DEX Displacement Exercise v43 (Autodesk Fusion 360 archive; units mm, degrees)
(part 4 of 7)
sketch "Sketch38" plane through (0, 0, 0) normal (0, 0, 1) x axis (1, 0, 0)
  line L1 (-32.5, 52.5) -> (-32.5, -27.5)
  line L2 (87.5, -27.5) -> (-32.5, -27.5)
  line L3 (-17.5, -17.5) -> (-17.5, -27.5)
  line L4 (17.5, -17.5) -> (-17.5, -17.5)
  line L5 (17.5, 17.5) -> (17.5, -17.5)
  line L6 (-17.5, 17.5) -> (17.5, 17.5)
  line L7 (-17.5, 27.5) -> (-17.5, 17.5)
  line L8 (-32.5, 27.5) -> (-17.5, 27.5)
  line L9 (87.5, -27.5) -> (-17.5, -27.5)
  line L10 (-32.5, 52.5) -> (-32.5, 27.5)
  line L11 (17.5, 0) -> (0, 0)
  line L12 (-32.8, -22.8) -> (-32.8, 22.8)
  line L13 (40.8319, 85.8319) -> (-15.5681, 85.8319)
  line L14 (40.8319, 29.4319) -> (40.8319, 85.8319)
  line L15 (-15.5681, 29.4319) -> (40.8319, 29.4319)
  line L16 (-15.5681, 85.8319) -> (-15.5681, 29.4319)
  line L17 (12.6319, 57.6319) -> (12.6319, 85.8319)
  line L18 (40.8319, 57.6319) -> (12.6319, 57.6319)
  line L19 (-17.6, 17.4) -> (17.4, 17.4)
  line L20 (-17.6, 27.4) -> (-17.6, 17.4)
  line L21 (-19.3, 27.4) -> (-17.6, 27.4)
  line L22 (-19.3, 15.7) -> (-19.3, 27.4)
  line L23 (15.7, 15.7) -> (-19.3, 15.7)
  line L24 (15.7, -15.7) -> (15.7, 15.7)
  line L25 (-19.3, -15.7) -> (15.7, -15.7)
  line L26 (-19.3, -27.4) -> (-19.3, -15.7)
  line L27 (-17.6, -27.4) -> (-19.3, -27.4)
  line L28 (-17.6, -17.4) -> (-17.6, -27.4)
  line L29 (17.4, -17.4) -> (-17.6, -17.4)
  line L30 (17.4, 17.4) -> (17.4, -17.4)
  line L31 (27.5, -27.4) -> (-17.6, -27.4)
  line L32 (27.5, 27.4) -> (27.5, -27.4)
  line L33 (-17.6, 27.4) -> (27.5, 27.4)
  line L34 (0, 0) -> (12.6319, 57.6319)
  line L35 (36.2019, 81.2019) -> (-10.9381, 81.2019)
  line L36 (36.2019, 34.0619) -> (36.2019, 81.2019)
  line L37 (-10.9381, 34.0619) -> (36.2019, 34.0619)
  line L38 (-10.9381, 81.2019) -> (-10.9381, 34.0619)
  line L39 (-17.5, 37.4) -> (-17.5, 27.5)
  line L40 (-32.5, 37.4) -> (-17.5, 37.4)
  line L41 (-40.5, 15.7) -> (-19.3, 15.7)
  line L42 (-40.5, 27.4) -> (-40.5, 15.7)
  line L43 (-19.3, 27.4) -> (-40.5, 27.4)
  line L44 (-40.5, -27.4) -> (-19.3, -27.4)
  line L45 (-40.5, -15.7) -> (-40.5, -27.4)
  line L46 (-19.3, -15.7) -> (-40.5, -15.7)
  line L47 (-40.5, -15.7) -> (-40.5, 15.7)
  line L48 (-19.3, 35.6) -> (-19.3, 27.4)
  line L49 (-40.5, 35.6) -> (-19.3, 35.6)
  line L50 (-40.5, 27.4) -> (-40.5, 35.6)
  line L51 (-40.5, 37.3) -> (-40.5, 35.6)
  line L52 (-17.6, 37.3) -> (-40.5, 37.3)
  line L53 (-17.6, 27.4) -> (-17.6, 37.3)
  line L54 (-17.6, -27.6) -> (-17.6, -27.4)
  line L55 (27.5, -27.6) -> (-17.6, -27.6)
  line L56 (27.5, -27.4) -> (27.5, -27.6)
  line L57 (27.5, -29.2) -> (27.5, -27.6)
  line L58 (-40.5, -29.2) -> (27.5, -29.2)
  line L59 (-40.5, -27.4) -> (-40.5, -29.2)
  line L60 (-19.3, -29.2) -> (-19.3, -27.4)
  line L61 (-27.1727, 28.6279) -> (8.2492, 62.2493)
  line L62 (36.6558, 14.6378) -> (18.5441, 59.9928)
  line L63 (-15.5681, 27.4) -> (-15.5681, 29.4319)
  line L64 (-17.6, 29.4319) -> (-15.5681, 29.4319)
  line L65 (-17.6, 47.4) -> (-17.6, 37.3)
  line L66 (-40.5, 47.4) -> (-17.6, 47.4)
  line L67 (-40.5, 37.3) -> (-40.5, 47.4)
  line L68 (-32.6, 47.4) -> (-32.6, 37.3)
  circle C1 centre (0, 0) radius 13.369
  circle C2 centre (0, 0) radius 39.4704
  circle C3 centre (-32.8, -22.8) radius 9.7
  circle C4 centre (-32.8, 22.8) radius 9.7
  circle C5 centre (12.6319, 57.6319) radius 6.3662
  circle C6 centre (0, 0) radius 21
  circle C7 centre (0, 0) radius 15
  circle C8 centre (-32.8, -22.8) radius 3
  circle C9 centre (-32.8, 22.8) radius 3
  circle C10 centre (-32.8, 22.8) radius 4.5
  circle C11 centre (-32.8, -22.8) radius 4.5
  circle C12 centre (0, 0) radius 19.5
  circle C13 centre (-12.5, -22.5) radius 2.7
  circle C14 centre (36.2019, 34.0619) radius 4
  circle C15 centre (0, 0) radius 15.369
  arc A1 centre (0, 0) radius 24.8793 clockwise from (-19.3, -15.7) to (-19.3, 15.7)
  circle C16 centre (22.5, -22.5) radius 2.7
  circle C17 centre (22.5, 22.5) radius 2.7
  circle C18 centre (-12.5, 22.5) radius 2.7
  circle C19 centre (-10.9381, 34.0619) radius 4
  circle C20 centre (-10.9381, 81.2019) radius 4
  circle C21 centre (36.2019, 81.2019) radius 4
  circle C22 centre (12.6319, 57.6319) radius 19
  circle C23 centre (-27.5, 42.4) radius 2.7
  circle C24 centre (-27.5, 42.4) radius 1.575
  circle C25 centre (-12.5, 22.5) radius 1.575
  circle C26 centre (22.5, 22.5) radius 1.575
  circle C27 centre (22.5, -22.5) radius 1.575
  circle C28 centre (-12.5, -22.5) radius 1.575
  circle C29 centre (-27.5, 42.4) radius 3.75
  circle C30 centre (-12.5, 22.5) radius 3.75
  circle C31 centre (22.5, 22.5) radius 3.75
  circle C32 centre (22.5, -22.5) radius 3.75
  circle C33 centre (-12.5, -22.5) radius 3.75
  point P5 (-17.5, -27.5)
  point P11 (-32.5, 27.5)
  point P6 (-17.5, -17.5)
  point P12 (0, 0)
  point P14 (0, 0)
  point P15 (17.5, 0)
  point P18 (-42.5, -22.8)
  point P19 (-32.8, -32.5)
  point P16 (-32.8, -22.8)
  point P17 (-32.8, 22.8)
  point P20 (-32.8, 22.8)
  point P21 (-32.8, -22.8)
  point P22 (-32.8, 0)
  point P28 (12.6319, 85.8319)
  point P30 (40.8319, 57.6319)
  point P27 (12.6319, 57.6319)
  point P29 (12.6319, 57.6319)
  point P33 (0, 17.5)
  point P32 (0, 0)
  point P38 (17.4, 17.4)
  point P50 (17.4, 17.4)
  point P40 (-17.6, 27.4)
  point P53 (-17.6, 27.4)
  point P56 (12.6319, 57.6319)
  point P57 (0, 0)
  point P62 (12.6319, 81.2019)
  point P63 (36.2019, 57.6319)
  point P60 (36.2019, 34.0619)
  point P64 (36.2019, 34.0619)
  point P66 (-32.5, 37.4)
  point P41 (-19.3, 27.4)
  point P70 (-19.3, 27.4)
  point P45 (-19.3, -15.7)
  point P73 (-19.3, -15.7)
  point P74 (-40.5, -15.7)
  point P72 (-40.5, -15.7)
  point P69 (-40.5, 27.4)
  point P77 (-40.5, 27.4)
  point P80 (-17.6, 27.4)
  point P51 (27.5, -27.4)
  point P83 (27.5, -27.4)
  point P71 (-40.5, -27.4)
  point P86 (-40.5, -27.4)
  point P87 (-19.3, -29.2)
  point P31 (0, 0)
  point P88 (0, 0)
  point P55 (-12.5, -22.5)
  point P91 (-12.5, 22.5)
  point P89 (22.5, -22.5)
  point P90 (22.5, 22.5)
  point P61 (-10.9381, 34.0619)
  point P92 (-10.9381, 34.0619)
  point P58 (-10.9381, 81.2019)
  point P93 (-10.9381, 81.2019)
  point P59 (36.2019, 81.2019)
  point P94 (36.2019, 81.2019)
  point P96 (8.2492, 62.2493)
  point P97 (-27.1727, 28.6279)
  point P98 (18.5441, 59.9928)
  point P99 (36.6558, 14.6378)
  point P1 (0, 0)
  point P67 (0, 0)
  point P101 (-15.5681, 27.4)
  point P102 (-17.6, 29.4319)
  point P78 (-40.5, 37.3)
  point P105 (-40.5, 37.3)
  point P106 (-32.6, 37.3)
  point P107 (-32.6, 47.4)
  point P3 (-32.5, -27.5)
  point P4 (87.5, -27.5)
  point P2 (-32.5, 52.5)
  point P7 (17.5, -17.5)
  point P8 (17.5, 17.5)
  point P9 (-17.5, 17.5)
  point P10 (-17.5, 27.5)
  point P23 (-15.5681, 85.8319)
  point P24 (40.8319, 85.8319)
  point P13 (0, 0)
  point P42 (-19.3, 15.7)
  point P49 (17.4, -17.4)
  point P48 (-17.6, -17.4)
  point P39 (-17.6, 17.4)
  point P65 (-17.5, 37.4)
  point P100 (-27.5, 42.4)
  vertical L1
  perpendicular L1 L2
  coincident L2 P5
  perpendicular L2 L3
  perpendicular L3 L4
  perpendicular L4 L5
  perpendicular L5 L6
  perpendicular L6 L7
  coincident L1 P11
  perpendicular L1 L8
  coincident P6 L7
  concentric C1 C2
  coincident P12 P14
  horizontal L11
  midpoint L5 P15
  equal C3 C4
  coincident C3 P18
  coincident C3 P19
  vertical P16 P19
  horizontal P16 P18
  vertical P16 P17
  coincident P17 P20
  coincident P16 P21
  midpoint L12 P22
  coincident L11 P22
  equal L13 L16
  midpoint L13 P28
  perpendicular L13 L17
  perpendicular L17 L18
  midpoint L14 P30
  coincident P27 P29
  concentric C2 C6
  concentric C2 C7
  midpoint L6 P33
  vertical P32 P33
  perpendicular L13 L16
  parallel L13 L15
  parallel L14 L16
  concentric C3 C8
  concentric C4 C9
  equal C8 C9
  concentric C4 C10
  concentric C3 C11
  equal C10 C11
  parallel L6 L19
  perpendicular L19 L20
  perpendicular L20 L21
  perpendicular L21 L22
  perpendicular L22 L23
  perpendicular L11 L24
  perpendicular L24 L25
  perpendicular L11 L26
  perpendicular L26 L27
  perpendicular L27 L28
  perpendicular L28 L29
  perpendicular L4 L30
  coincident P38 P50
  perpendicular L28 L31
  perpendicular L2 L32
  perpendicular L32 L33
  coincident P40 P53
  concentric C1 C12
  coincident P27 P56
  coincident P12 P57
  perpendicular L35 L36
  parallel L35 L37
  parallel L36 L38
  perpendicular L17 L35
  midpoint L35 P62
  midpoint L36 P63
  coincident L17 P62
  coincident L18 P63
  equal L35 L36
  coincident P60 P64
  perpendicular L8 L39
  coincident L10 P66
  horizontal L40
  concentric C2 C15
  perpendicular L22 L41
  perpendicular L23 L42
  perpendicular L22 L43
  coincident P41 P70
  perpendicular L26 L44
  perpendicular L44 L45
  perpendicular L45 L46
  coincident P45 P73
  coincident L46 P74
  perpendicular L46 L47
  coincident P72 P74
  perpendicular L21 L48
  perpendicular L48 L49
  perpendicular L21 L50
  coincident P69 P77
  perpendicular L49 L51
  perpendicular L50 L52
  perpendicular L49 L53
  coincident P53 P80
  perpendicular L2 L54
  perpendicular L54 L55
  perpendicular L55 L56
  coincident P51 P83
  perpendicular L55 L57
  perpendicular L57 L58
  perpendicular L58 L59
  coincident P71 P86
  coincident L58 P87
  perpendicular L58 L60
  coincident P31 P88
  vertical P55 P91
  vertical P89 P90
  horizontal P55 P89
  horizontal P90 P91
  equal C13 C18
  equal C13 C17
  equal C13 C16
  horizontal L37
  coincident P61 P92
  coincident P58 P93
  coincident P59 P94
  concentric C5 C22
  equal C14 C19
  equal C14 C21
  equal C14 C20
  coincident C5 P96
  coincident C2 P97
  coincident C5 P98
  coincident C2 P99
  tangent C2 L61
  tangent C5 L61
  tangent C5 L62
  tangent C2 L62
  coincident P1 P67
  equal C18 C23
  coincident L33 P101
  perpendicular L33 L63
  coincident L53 P102
  perpendicular L53 L64
  equal L63 L64
  perpendicular L40 L65
  perpendicular L1 L66
  perpendicular L40 L67
  coincident P78 P105
  coincident L52 P106
  perpendicular L52 L68
  coincident L66 P107
  concentric C23 C24
  concentric C18 C25
  concentric C17 C26
  concentric C16 C27
  concentric C13 C28
  equal C27 C28
  equal C26 C28
  equal C25 C28
  equal C24 C28
  concentric C24 C29
  concentric C18 C30
  concentric C17 C31
  concentric C16 C32
  concentric C13 C33
  equal C32 C33
  equal C31 C33
  equal C30 C33
  equal C29 C33
  dimension "d1457" distance P3 P4 = 120
  dimension "d1458" distance P2 P3 = 80
  dimension "d1459" distance P5 P6 = 10
  dimension "d1462" distance P7 P8 = 35
  dimension "d1463" distance P9 P10 = 10
  dimension "d1473" diameter C1 = 26.738 (= "pd_maindrive")
  dimension "d1474" diameter C2 = 78.9409 (= "pd_drive")
  dimension "d1475" diameter C4 = 19.4 (= "od_bearings + ( 2 * 1.7 ) * 1 mm")
  dimension "d1476" distance L1 P18 = 10
  dimension "d1477" distance L2 P19 = 5
  dimension "d1478" distance P23 P24 = 56.4
  dimension "d1479" diameter C5 = 12.7324 (= "pd_pinion")
  dimension "d1480" distance P13 P27 = 59 (= "c_dist_manuel")
  dimension "d1481" diameter C6 = 42
  dimension "d1482" diameter C7 = 30
  dimension "d1484" diameter C8 = 6 (= "hw_m4insert_d")
  dimension "d1485" diameter C11 = 9
  dimension "d1486" distance L7 L20 = 0.1
  dimension "d1487" distance L8 L21 = 0.1 (= "d1486")
  dimension "d1488" distance L6 L19 = 0.1 (= "d1486")
  dimension "d1489" distance P8 L30 = 0.1 (= "d1486")
  dimension "d1490" distance P7 L29 = 0.1 (= "d1486")
  dimension "d1491" distance P6 L28 = 0.1 (= "d1486")
  dimension "d1492" distance P40 L22 = 1.7
  dimension "d1493" distance L19 P42 = 1.7
  dimension "d1494" distance L24 P50 = 1.7
  dimension "d1495" distance L25 P49 = 1.7
  dimension "d1496" distance L26 P48 = 1.7
  dimension "d1497" distance P7 L32 = 10
  dimension "d1498" distance P5 L31 = 0.1
  dimension "d1508" distance C6 C12 = 1.5
  dimension "d1512" distance L3 P55 = 5
  dimension "d1514" diameter C13 = 5.4 (= "hw_m3insert_d")
  dimension "d1516" distance P58 P59 = 47.14
  dimension "d1517" diameter C14 = 8
  dimension "d1518" distance P39 P65 = 20
  dimension "d1519" distance C1 C15 = 2
  dimension "d1528" distance L1 L42 = 8
  dimension "d1546" distance L49 L52 = 1.7
  dimension "d1547" distance P66 L52 = 0.1
  dimension "d1548" distance P5 L55 = 0.1
  dimension "d1549" distance L2 L58 = 1.7
  dimension "d1556" distance L6 P91 = 5
  dimension "d1557" distance L5 P89 = 5
  dimension "d1591" diameter C22 = 38
  dimension "d1595" distance L1 L3 = 15
  dimension "d1596" distance P3 P7 = 50
  dimension "d1633" distance L2 P55 = 5
  dimension "d1634" distance L40 P100 = 5
  dimension "d1635" distance L10 P100 = 5
  dimension "d1637" distance P100 L66 = 5
  dimension "d1638" distance L10 L68 = 0.1
  dimension "d1721" diameter C28 = 3.15
  dimension "d1722" diameter C33 = 7.5
  dimension "d900" distance = 6
  dimension "d902" distance = 3.7 (= "2 mm + 1.2 mm + 0.5 mm")
  dimension "d903" distance = 1
  dimension "d904" distance = 8
  dimension "d905" distance = 2.54
  dimension "d906" distance = 2.54
  dimension "d907" distance = 2.54
  dimension "d908" Side1Offset = 0
  dimension "d909" TaperAngle = 0
  dimension "d910" ProfileOffset = 0
  dimension "d911" Side1Offset = 0
  dimension "d912" TaperAngle = 0
  dimension "d913" leftDistance = 1.5
  dimension "d915" distance = 5.65
  dimension "d916" distance = 14.65
  dimension "d917" distance = 14.65
  dimension "d918" Side1Offset = 0
  dimension "d919" TaperAngle = 0
  dimension "d920" ChordLen = 4
  dimension "d921" ChordLen = 1
  dimension "d923" distance = 2.54
  dimension "d924" Radius = 2
  dimension "d729" diameter = 4
  dimension "d730" diameter = 6 (= "hw_m4insert_d")
  dimension "d731" diameter = 16 (= "od_bearings")
  dimension "d732" distance = 1
  dimension "d733" distance = 0.25
  dimension "d734" AlongDistance = -26
  dimension "d735" TaperAngle = 0
  dimension "d736" ProfileOffset = 0.5
  dimension "d737" AlongDistance = 5 (= "t_bearings")
  dimension "d738" TaperAngle = 0
  dimension "d739" distance = 6
  dimension "d740" ProfileOffset = 0
  dimension "d741" Side1Offset = 0
  dimension "d742" TaperAngle = 0
  dimension "d743" Radius = 4
  dimension "d744" distance = -1
  dimension "d745" AlongDistance = 32
  dimension "d746" TaperAngle = 0
  dimension "d747" distance = 0.5
  dimension "d748" distance = 1
  dimension "d749" ProfileOffset = 0
  dimension "d750" AlongDistance = 3
  dimension "d751" TaperAngle = 0
  dimension "d752" ProfileOffset = 0
  dimension "d753" Side1Offset = 0
  dimension "d754" TaperAngle = 0
  dimension "d755" Side1Offset = 0
  dimension "d756" TaperAngle = 0
  dimension "d757" ProfileOffset = 0
  dimension "d758" Side1Offset = 0
  dimension "d759" TaperAngle = 0
  dimension "d760" AlongDistance = 12
  dimension "d761" TaperAngle = 0
  dimension "d762" AlongDistance = -37
  dimension "d763" TaperAngle = 0
  dimension "d764" Side1Offset = 0.5
  dimension "d765" TaperAngle = 0
  dimension "d767" Radius = 3
  dimension "d768" Radius = 2
  dimension "d770" Radius = 3
  dimension "d771" Radius = 3
  dimension "d772" distance = 3
  dimension "d773" distance = 3
  dimension "d774" Radius = 1
  dimension "d775" Radius = 0.5
  dimension "d776" Radius = 2
  dimension "d777" diameter = 5.4 (= "hw_m3insert_d")
  dimension "d778" diameter = 3.5 (= "hw_m3_thru")
  dimension "d779" Side1Offset = 0
  dimension "d780" TaperAngle = 0
  dimension "d781" Side1Offset = 0
  dimension "d782" TaperAngle = 0
  dimension "d783" Radius = 2
  dimension "d784" Radius = 2
  dimension "d785" Radius = 2
  dimension "d786" Radius = 3
  dimension "d788" Radius = 0.5
  dimension "d789" distance = 12
  dimension "d790" distance = 2
  dimension "d791" angle = 45
  dimension "d793" Radius = 2
  dimension "d794" Radius = 2
  dimension "d795" Radius = 1
  dimension "d797" Radius = 2
  dimension "d798" Radius = 1
  dimension "d799" Radius = 2
  dimension "d800" Radius = 4.5
  dimension "d801" distance = 0.275 (= "preload_bearings / 2")
  dimension "d803" distance = -0.5
  dimension "d806" distance = 3
  dimension "d807" AlongDistance = -60
  dimension "d808" distance = 3.8274 (= "d430 / 2")
  dimension "d809" distance = 0.423 (= "1 mm - 0.577 mm")
  dimension "d810" distance = 0.5
  dimension "d813" Side1Offset = 0
  dimension "d814" TaperAngle = 0
  dimension "d815" distance = 0.1
  dimension "d816" distance = 1.75
  dimension "d818" distance = 35
  dimension "d820" distance = 5
  dimension "d821" distance = 5
  dimension "d822" diameter = 4.064 (= "hw_n6_thru")
  dimension "d823" diameter = 6.6548 (= "hw_n6_flathead")
  dimension "d824" distance = 0.6
  dimension "d825" distance = 0.6 (= "d824")
  dimension "d827" TaperAngle = 0
  dimension "d828" diameter = 3.1 (= "hw_n6_thread")
  dimension "d829" Side1Offset = 0
  dimension "d830" TaperAngle = 0
  dimension "d831" distance = 4
  dimension "d832" distance = 4.477 (= "d833")
  dimension "d833" distance = 4.477 (= "d477")
  dimension "d836" diameter = 6.6548 (= "hw_n6_flathead")
  dimension "d839" Side1Offset = 0
  dimension "d840" TaperAngle = 0
  dimension "d841" distance = 0.9
  dimension "d842" angle = 50
  dimension "d843" angle = 50
  dimension "d844" distance = 8
  dimension "d845" distance = 5
  dimension "d846" diameter = 4.5
  dimension "d847" AlongDistance = -7
  dimension "d848" TaperAngle = 0
  dimension "d849" leftDistance = 0.75
  dimension "d850" ProfileOffset = 0
  dimension "d851" Side1Offset = 0
  dimension "d852" TaperAngle = 0
  dimension "d853" ProfileOffset = 0
  dimension "d854" Side1Offset = 0
  dimension "d855" TaperAngle = 0
  dimension "d856" distance = 12.7
  dimension "d857" leftDistance = 1.5
  dimension "d858" distance = 1.5454
  dimension "d859" Radius = 4
  dimension "d860" Radius = 2
  dimension "d861" Radius = 2
  dimension "d862" Radius = 4
  dimension "d863" Radius = 2
  dimension "d864" Radius = 35
  dimension "d865" Radius = 4
  dimension "d866" Radius = 1
  dimension "d869" Side1Offset = 0
  dimension "d870" TaperAngle = 0
  dimension "d872" distance = 1.5
  dimension "d873" leftDistance = 1.5
  dimension "d874" Radius = 2
  dimension "d885" distance = 27.775
  dimension "d886" distance = 30.275 (= "30 mm + preload_bearings / 2")
  dimension "d889" diameter = 3.3 (= "hw_m4_tappedwj")
  dimension "d890" distance = 5
  dimension "d891" distance = 10.275 (= "10 mm + preload_bearings / 2")
  dimension "d893" TaperAngle = 0
  dimension "d894" distance = 17.5
  dimension "d895" distance = 27.5
  dimension "d896" distance = 0.2
  dimension "d897" distance = 0.2 (= "d896")
extrude "Extrude164" new body sketch "Sketch38" profile of L10 C6 C7 C8 C9 C10 C11 L19 L20 L21 L22 L23 L24 L25 L26 L27 L28 L29 L30 L31 L32 L33 C12 C13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 to an object offset -0.5 from offset -20
extrude "Extrude165" cut sketch "Sketch38" profile of L10 C6 L19 L20 L28 L29 L30 L31 L32 L33 C12 C13 L52 L54 L55 L56 C16 C17 C18 C23 L65 L66 L68 against normal blind 3.35 (magnitude of "-t_sheet_MAIN / 2")
extrude "Extrude169" cut sketch "Sketch38" profile of C6 C7 L23 L24 L25 C12 C15 L41 L46 L47 A1 against normal blind 8
extrude "Extrude171" cut sketch "Sketch38" profile of C8 C9 C10 C11 L22 L26 L41 L42 L43 L44 L45 L46 L47 L48 L49 L50 L58 L59 L60 A1 against normal blind 10
extrude "Extrude172" sketch "Sketch38" profile of C8 C9 no distance stored
sketch "Sketch39" plane through (0, 0, -10) normal (0, 0, 1) x axis (-1, 0, 0)
  line L1 (19.3, -35.6) -> (19.3, -15.7)
  line L2 (40.5, -35.6) -> (19.3, -35.6)
  line L3 (40.5, 29.2) -> (40.5, -35.6)
  line L4 (19.3, 29.2) -> (40.5, 29.2)
  line L5 (19.3, 15.7) -> (19.3, 29.2)
  line L6 (37.13, 14.8) -> (24.8, 14.8)
  line L7 (37.13, -14.8) -> (37.13, 14.8)
  line L8 (35.13, -14.8) -> (37.13, -14.8)
  line L9 (35.13, 12.8) -> (35.13, -14.8)
  line L10 (21.8, 12.8) -> (35.13, 12.8)
  line L11 (21.8, 29.2) -> (21.8, 12.8)
  line L12 (24.8, 14.8) -> (24.8, 29.2)
  line L13 (21.8, 36.8) -> (21.8, 29.2)
  line L14 (40.5, 36.8) -> (40.5, 29.2)
  line L15 (21.8, 36.8) -> (40.5, 36.8)
  line L16 (24.8, 36.8) -> (24.8, 29.2)
  line L17 (19.3, 36.8) -> (21.8, 36.8)
  line L18 (19.3, 29.2) -> (19.3, 36.8)
  line L19 (-27.5, 36.8) -> (19.3, 36.8)
  line L20 (-27.5, 29.2) -> (-27.5, 36.8)
  line L21 (19.3, 29.2) -> (-27.5, 29.2)
  circle C1 centre (32.8, 22.8) radius 3
  circle C2 centre (32.8, -22.8) radius 3
  arc A1 centre (0, 0) radius 24.8793 clockwise from (19.3, 15.7) to (19.3, -15.7)
  circle C3 centre (19.8, 30.8) radius 2.5
  point P18 (21.8, 29.2)
  point P19 (24.8, 29.2)
  point P12 (24.8, 14.8)
  point P20 (24.8, 14.8)
  point P7 (40.5, 29.2)
  point P25 (40.5, 29.2)
  point P24 (21.8, 36.8)
  point P27 (21.8, 36.8)
  point P29 (24.8, 36.8)
  point P31 (19.3, 29.2)
  point P32 (19.3, 29.2)
  point P35 (19.3, 29.2)
  point P36 (-27.5, 29.2)
  point P11 (19.8, 30.8)
  point P22 (32.8, -22.8)
  point P23 (32.8, 22.8)
  point P28 (32.8, 22.8)
  perpendicular L3 L6
  perpendicular L6 L7
  perpendicular L7 L8
  perpendicular L8 L9
  perpendicular L9 L10
  coincident L4 P18
  perpendicular L4 L11
  coincident L4 P19
  perpendicular L4 L12
  coincident P12 P20
  perpendicular L4 L13
  coincident P7 P25
  perpendicular L4 L14
  perpendicular L14 L15
  coincident P24 P27
  coincident L15 P29
  perpendicular L15 L16
  perpendicular L13 L17
  perpendicular L17 L18
  coincident P31 P32
  perpendicular L18 L19
  perpendicular L19 L20
  perpendicular L20 L21
  coincident P31 P35
  coincident L20 P36
  dimension "d1574" diameter C3 = 5
  dimension "d1597" distance P11 L11 = 2
  dimension "d1598" distance L3 L7 = 3.37
  dimension "d1599" distance L11 L12 = 3
  dimension "d1600" distance L6 L10 = 2
  dimension "d1601" distance L7 L9 = 2
  dimension "d1603" distance L8 P22 = 8
  dimension "d1604" distance L6 P23 = 8
  dimension "d1605" distance L12 P23 = 8
  dimension "d1606" distance L15 P28 = 14
  dimension "d1607" distance P11 P23 = 8
extrude "Extrude175" cut sketch "Sketch39" profile of L4 L5 C3 L6 L7 L8 L9 L10 L11 L12 L21 no distance stored
extrude "Extrude179" add sketch "Sketch39" profile of L4 C3 L13 L14 L15 L16 L17 L18 L19 L20 L21 to an object
extrude "Extrude180" add sketch "Sketch39" profile of L4 L5 C3 L13 L18 L21 to an object offset 8.5
sketch "Sketch42" plane through (-40.5, 0, 0) normal (-1, 0, 0) x axis (0, -1, 0)
  line L1 (-35.6, -10) -> (36.8, -10)
  line L2 (-35.6, -0.5) -> (-35.6, -10)
  line L3 (-47.4, -0.5) -> (-35.6, -0.5)
  line L4 (36.8, -20) -> (-47.4, -20)
  line L5 (36.8, -10) -> (36.8, -20)
  line L6 (36.8, -15) -> (30.8, -15)
  line L7 (-47.4, -20) -> (-47.4, -0.5)
  circle C1 centre (30.8, -15) radius 2.7
  circle C2 centre (30.8, -15) radius 1.625
  circle C3 centre (30.8, -15) radius 3.7
  point P8 (30.8, -15)
  point P9 (30.8, -15)
  point P10 (36.8, -15)
  point P12 (30.8, -15)
  point P11 (22.8, -10)
  coincident P8 P9
  horizontal L6
  midpoint L5 P10
  coincident P9 P12
  concentric C2 C3
  dimension "d1619" diameter C1 = 5.4 (= "hw_m3insert_d")
  dimension "d1620" distance P8 P11 = 8
  dimension "d1621" diameter C2 = 3.25
  dimension "d1626" distance C1 C3 = 1
extrude "Extrude181" cut sketch "Sketch42" profile of C2 to an object
extrude "Extrude182" cut sketch "Sketch42" profile of C1 C2 against normal blind 8
extrude "Extrude183" cut sketch "Sketch42" profile of C1 C3 against normal blind 3
chamfer "Chamfer40" distance 1
chamfer "Chamfer41" distance 0.5
chamfer "Chamfer42" distance 0.5
chamfer "Chamfer39" distance 0.5
fillet "Fillet113" radius 0.3
fillet "Fillet114" radius 1
fillet "Fillet115" radius 2
fillet "Fillet116" radius 3
sketch "Revolves" plane through (0, 0, 0) normal (1, 0, 0) x axis (0, 1, 0)
  line L1 (0, -35) -> (0, 0)
  line L2 (15, -20) -> (21, -20)
  line L3 (15, -13) -> (15, -20)
  line L4 (21, -13) -> (15, -13)
  line L5 (21, -20) -> (21, -13)
  line L6 (19.5, -11.8) -> (19.5, -13)
  line L7 (15.7, -8) -> (19.5, -11.8)
  line L8 (16.5, -21.5) -> (16.5, -20)
  line L9 (41.4704, -21.5) -> (16.5, -21.5)
  line L10 (41.4704, -29.5) -> (41.4704, -21.5)
  line L11 (0, -29.5) -> (41.4704, -29.5)
  line L12 (0, -17) -> (15, -17)
  line L13 (0, -16) -> (15, -16)
  line L14 (15.75, -12.75) -> (15, -13.5)
  line L15 (15.75, -11.75) -> (15.75, -12.75)
  line L16 (13.369, -9.369) -> (15.75, -11.75)
  line L17 (13.369, 0) -> (13.369, -9.369)
  line L18 (0, 0) -> (13.369, 0)
  line L19 (15.7, 0) -> (15.7, -8)
  line L20 (13.369, 0) -> (15.7, 0)
  line L21 (0, 16) -> (15, 16)
  line L22 (15, 13) -> (15, 20)
  line L23 (15.75, 12.75) -> (15, 13.5)
  line L24 (15.75, 11.75) -> (15.75, 12.75)
  line L25 (13.369, 9.369) -> (15.75, 11.75)
  line L26 (13.369, 0) -> (13.369, 9.369)
  line L27 (0, 0) -> (13.369, 0)
  line L28 (21, 13) -> (15, 13)
  line L29 (21, 20) -> (21, 13)
  line L30 (15, 20) -> (21, 20)
  line L31 (0, 16) -> (0, 0)
  line L32 (0, 17) -> (15, 17)
  line L33 (0, 25) -> (0, 17)
  line L34 (16.5, 25) -> (0, 25)
  line L35 (16.5, 20) -> (16.5, 25)
  line L36 (7.5, -16) -> (7.5, 16)
  line L37 (11.2, -15) -> (11.2, -16)
  line L38 (10.2, -14) -> (11.2, -15)
  line L39 (10.2, -10) -> (10.2, -14)
  line L40 (9.125, -8.925) -> (10.2, -10)
  line L41 (9.125, 0) -> (9.125, -8.925)
  line L42 (9.125, -17.5) -> (9.625, -17)
  line L43 (9.125, -20) -> (9.125, -17.5)
  line L44 (11.25, -22.125) -> (9.125, -20)
  line L45 (11.25, -29.5) -> (11.25, -22.125)
  line L46 (7.5, -29.5) -> (7.5, -17)
  line L47 (11.25, 29.5) -> (11.25, 22.125)
  line L48 (11.25, 22.125) -> (9.125, 20)
  line L49 (7.5, 29.5) -> (7.5, 17)
  line L50 (9.125, 20) -> (9.125, 17.5)
  line L51 (9.125, 17.5) -> (9.625, 17)
  line L52 (11.2, 15) -> (11.2, 16)
  line L53 (10.2, 14) -> (11.2, 15)
  line L54 (10.2, 10) -> (10.2, 14)
  line L55 (9.125, 8.925) -> (10.2, 10)
  line L56 (9.125, 0) -> (9.125, 8.925)
  line L57 (11.569, -7.569) -> (13.369, -9.369)
  line L58 (11.569, -11.75) -> (11.569, -7.569)
  line L59 (15.75, -11.75) -> (11.569, -11.75)
  line L60 (15, -19.5) -> (15.5, -20)
  point P1 (0, 0)
  point P2 (0, 0)
  point P8 (19.5, -13)
  point P10 (15.7, -8)
  point P11 (15.7, -8)
  point P12 (16.5, -20)
  point P16 (0, -29.5)
  point P17 (15, -17)
  point P18 (0, -17)
  point P19 (15, -16)
  point P20 (0, -16)
  point P21 (15, -16.5)
  point P22 (15, -13.5)
  point P27 (0, 0)
  point P26 (13.369, 0)
  point P29 (13.369, 0)
  point P4 (21, -20)
  point P41 (21, 20)
  point P5 (15, -20)
  point P32 (15, 20)
  point P6 (15, -13)
  point P33 (15, 13)
  point P7 (21, -13)
  point P40 (21, 13)
  point P30 (15, 16)
  point P31 (0, 16)
  point P34 (15, 13.5)
  point P23 (15.75, -12.75)
  point P35 (15.75, 12.75)
  point P24 (15.75, -11.75)
  point P36 (15.75, 11.75)
  point P25 (13.369, -9.369)
  point P37 (13.369, 9.369)
  point P38 (13.369, 0)
  point P39 (0, 0)
  point P42 (15, 17)
  point P46 (16.5, 20)
  point P47 (7.5, 16)
  point P48 (7.5, -16)
  point P49 (11.2, -16)
  point P54 (9.125, 0)
  point P55 (9.625, -17)
  point P59 (11.25, -29.5)
  point P53 (9.125, -8.925)
  point P60 (7.5, -17)
  point P61 (7.5, -29.5)
  point P69 (11.2, 16)
  point P50 (11.2, -15)
  point P70 (11.2, 15)
  point P51 (10.2, -14)
  point P71 (10.2, 14)
  point P52 (10.2, -10)
  point P72 (10.2, 10)
  point P73 (9.125, 8.925)
  point P74 (9.125, 0)
  point P68 (9.625, 17)
  point P56 (9.125, -17.5)
  point P67 (9.125, 17.5)
  point P57 (9.125, -20)
  point P64 (9.125, 20)
  point P58 (11.25, -22.125)
  point P62 (11.25, 22.125)
  point P63 (11.25, 29.5)
  point P65 (7.5, 17)
  point P66 (7.5, 29.5)
  point P77 (15.75, -11.75)
  point P78 (15.5, -20)
  point P79 (15, -19.5)
  point P3 (0, -35)
  point P14 (41.4704, -21.5)
  point P15 (41.4704, -29.5)
  point P13 (16.5, -21.5)
  point P43 (0, 17)
  coincident P1 P2
  vertical L1
  horizontal L2
  vertical L3
  horizontal L4
  vertical L5
  coincident L4 P8
  perpendicular L4 L6
  coincident P10 P11
  coincident L2 P12
  perpendicular L2 L8
  perpendicular L8 L9
  perpendicular L2 L10
  coincident L1 P16
  perpendicular L1 L11
  coincident L3 P17
  coincident L1 P18
  perpendicular L1 L12
  coincident L3 P19
  coincident L1 P20
  perpendicular L1 L13
  midpoint L3 P21
  coincident L3 P22
  perpendicular L4 L15
  perpendicular L14 L16
  vertical L17
  perpendicular L17 L18
  coincident P1 P27
  vertical L19
  perpendicular L19 L20
  coincident P26 P29
  symmetric P4 L20 P41
  symmetric P5 L20 P32
  symmetric P6 L20 P33
  symmetric P7 L20 P40
  symmetric P19 L20 P30
  symmetric P20 L20 P31
  symmetric P22 L20 P34
  symmetric P23 L20 P35
  symmetric P24 L20 P36
  symmetric P25 L20 P37
  symmetric P26 L20 P38
  symmetric P27 L20 P39
  coincident L22 P42
  perpendicular L22 L32
  perpendicular L21 L33
  perpendicular L33 L34
  coincident L30 P46
  perpendicular L30 L35
  coincident P31 L33
  coincident L21 P47
  coincident L13 P48
  perpendicular L13 L36
  coincident L13 P49
  perpendicular L13 L37
  perpendicular L13 L39
  parallel L38 L40
  coincident L27 P54
  perpendicular L27 L41
  coincident L12 P55
  perpendicular L12 L43
  coincident L11 P59
  perpendicular L11 L45
  coincident P53 L43
  coincident L12 P60
  coincident L11 P61
  perpendicular L11 L46
  coincident P48 L46
  symmetric L18 P49 P69
  symmetric L18 P50 P70
  symmetric L18 P51 P71
  symmetric L18 P52 P72
  symmetric L18 P53 P73
  symmetric L18 P54 P74
  symmetric L18 P55 P68
  symmetric L18 P56 P67
  symmetric L18 P57 P64
  symmetric L18 P58 P62
  symmetric L18 P59 P63
  symmetric L18 P60 P65
  symmetric L18 P61 P66
  parallel L16 L57
  parallel L17 L58
  perpendicular L17 L59
  coincident P24 P77
  coincident L2 P78
  coincident L3 P79
  dimension "d1642" distance P2 P3 = 35
  dimension "d1643" distance P4 P7 = 7
  dimension "d1644" distance P1 L3 = 15 (= "( 30 / 2 ) * 1 mm")
  dimension "d1645" distance P1 L5 = 21 (= "( 42 / 2 ) * 1 mm")
  dimension "d1646" distance P1 P4 = 20
  dimension "d1647" distance P7 L6 = 1.5
  dimension "d1648" angle L6 L7 = 45
  dimension "d1649" distance P14 P15 = 8
  dimension "d1650" distance P3 L10 = 41.4704 (= "pd_drive / 2 + 2 mm")
  dimension "d1651" distance P5 L8 = 1.5
  dimension "d1652" distance P12 P13 = 1.5
  dimension "d1653" distance L12 P21 = 0.5
  dimension "d1654" distance L13 P21 = 0.5 (= "d1653")
  dimension "d1655" distance L4 P22 = 0.5
  dimension "d1657" angle L3 L14 = 45
  dimension "d1658" distance L3 L15 = 0.75
  dimension "d1659" distance P23 P24 = 1
  dimension "d1660" distance P1 L17 = 13.369 (= "( pd_maindrive / 2 mm ) * 1 mm")
  dimension "d1662" = 8.9592
  dimension "d1663" distance L21 L32 = 1 (= "d1653 * 2")
  dimension "d1664" distance L22 L35 = 1.5
  dimension "d1665" distance P43 L34 = 8
  dimension "d1666" distance L1 L36 = 7.5
  dimension "d1667" distance L36 L41 = 1.625 (= "( 3.25 / 2 ) * 1 mm")
  dimension "d1668" distance L36 L39 = 2.7 (= "hw_m3insert_d / 2")
  dimension "d1669" distance L37 L39 = 1
  dimension "d1670" angle L38 L39 = 45
  dimension "d1671" distance P51 P52 = 4
  dimension "d1672" distance L13 P51 = 2
  dimension "d1673" angle L43 L44 = 45
  dimension "d1674" angle L42 L43 = 45
  dimension "d1675" distance L12 P56 = 0.5
  dimension "d1676" distance L45 L46 = 3.75 (= "( 7.5 / 2 ) * 1 mm")
  dimension "d1677" distance P52 P57 = 10
  dimension "d1696" distance L17 L58 = 1.8
  dimension "d1855" angle L3 L60 = 45
  dimension "d1856" distance P5 P79 = 0.5
revolve "Revolve1" sketch "Revolves" AlongAngle 360
revolve "Revolve2" sketch "Revolves" AlongAngle 360 bodies "Drive Reduce", "Drive Pinion", "Drive Cap"
chamfer "Chamfer43" distance 0.5
sketch "Sketch44" plane through (0, 0, 0) normal (0, 0, 1) x axis (1, 0, 0)
  line L1 (0, 0) -> (0, 14.869)
  line L2 (1.6648, 14.7755) -> (0, 0)
  circle C1 centre (0, 0) radius 14.869
  circle C2 centre (0, 0) radius 13.369
  circle C3 centre (0, 0) radius 12.988
  arc A1 centre (0, 12.698) radius 0.85 clockwise from (0.7739, 12.3464) to (0, 11.848)
  arc A2 centre (-0.61, 12.9751) radius 1.52 clockwise from (0.8898, 12.7279) to (0.7739, 12.3464)
  arc A3 centre (1.1364, 12.6872) radius 0.25 clockwise from (0.8898, 12.7279) to (1.1587, 12.9362)
  point P1 (0, 0)
  point P2 (0, 0)
  point P3 (0, 14.869)
  point P4 (0, 0)
  point P5 (0, 0)
  point P6 (1.6648, 14.7755)
  point P10 (0, 11.848)
  point P9 (0, 12.698)
  point P14 (1.1587, 12.9362)
  point P16 (0, 12.988)
  point P13 (-0.61, 12.9751)
  coincident P1 P2
  coincident C1 P3
  vertical L1
  coincident P1 P4
  coincident P1 P5
  coincident C1 P6
  concentric C1 C2
  concentric C1 C3
  coincident L1 P10
  coincident L1 P9
  tangent A1 A2
  coincident C3 P14
  tangent A2 A3
  tangent C3 A3
  coincident C3 P16
  coincident L1 P16
  dimension "d1680" diameter C1 = 29.738 (= "pd_maindrive + 3 mm")
  dimension "d1681" diameter C2 = 26.738 (= "pd_maindrive")
  dimension "d1682" distance C2 C3 = 0.381
  dimension "d1683" angle L1 L2 = 6.429 (= "( 180 / nt_maindrive ) * 1 deg")
  dimension "d1684" distance L1 P13 = 0.61
  dimension "d1685" radius A2 = 1.52
  dimension "d1686" radius A1 = 0.85
  dimension "d1687" radius A3 = 0.25
  dimension "d1688" distance P10 P16 = 1.14
extrude "Extrude185" new body sketch "Sketch44" profile of C1 L1 L2 C3 A1 A2 A3 to an object Side2Offset 0
offset_faces "OffsetFaces14" distance 0.05
offset_faces "OffsetFaces15" distance -0.05
mirror "Mirror14"
combine "Combine23"
circular_pattern "C-Pattern1" TotalAngle 360
combine "Combine24"
combine "Combine25"
revolve "Revolve3" sketch "Revolves" AlongAngle 360
mirror "Mirror15"
combine "Combine26"
sketch "Sketch45" plane through (0, 0, 0) normal (0, 0, 1) x axis (1, 0, 0)
  line L1 (0, 43.4704) -> (0, 0)
  line L2 (1.1012, 43.4565) -> (0, 0)
  circle C1 centre (0, 0) radius 39.4704
  circle C2 centre (0, 0) radius 43.4704
  circle C3 centre (0, 0) radius 39.2164
  arc A1 centre (0, 39.0214) radius 0.555 clockwise from (0.4989, 38.7782) to (0, 38.4664)
  arc A2 centre (-0.4, 39.2164) radius 1 clockwise from (0.5906, 39.0799) to (0.4989, 38.7782)
  arc A3 centre (0.7392, 39.0594) radius 0.15 clockwise from (0.5906, 39.0799) to (0.7421, 39.2094)
  point P1 (0, 0)
  point P2 (0, 0)
  point P3 (0, 0)
  point P4 (0, 0)
  point P5 (0, 0)
  point P6 (0, 43.4704)
  point P7 (0, 0)
  point P8 (1.1012, 43.4565)
  point P9 (0, 38.4664)
  point P14 (0.7421, 39.2094)
  point P16 (0, 39.2164)
  point P11 (0, 39.0214)
  point P13 (-0.4, 39.2164)
  coincident P1 P2
  coincident P1 P3
  coincident P1 P4
  coincident P1 P5
  coincident C2 P6
  vertical L1
  coincident P2 P7
  coincident C2 P8
  coincident L1 P9
  coincident C3 P14
  tangent A1 A2
  tangent A2 A3
  tangent C3 A3
  coincident C3 P16
  coincident L1 P16
  coincident L1 P11
  dimension "d1699" diameter C1 = 78.9409 (= "pd_drive")
  dimension "d1700" distance C1 C2 = 4
  dimension "d1701" distance C1 C3 = 0.254
  dimension "d1702" angle L1 L2 = 1.452 (= "( 180 / nt_drive ) * 1 deg")
  dimension "d1703" radius A1 = 0.555
  dimension "d1704" radius A2 = 1
  dimension "d1705" radius A3 = 0.15
  dimension "d1706" distance P13 P16 = 0.4
  dimension "d1707" distance P9 P16 = 0.75
extrude "Extrude186" sketch "Sketch45" profile of C2 C3 L1 L2 A1 A2 A3 to an object
offset_faces "OffsetFaces12" distance 0.05
offset_faces "OffsetFaces13" distance -0.05
mirror "Mirror16"
combine "Combine27"
circular_pattern "C-Pattern2" TotalAngle 360
combine "Combine28"
combine "Combine29"
revolve "Revolve4" sketch "Revolves" AlongAngle 360
circular_pattern "C-Pattern3" TotalAngle 360
mirror "Mirror13"
extrude "Extrude190" sketch "Sketch38" profile of C8 C9 C10 C11 blind 4.25
chamfer "Chamfer49" distance 0.5
extrude "Extrude184" cut sketch "Sketch38" profile of C24 C25 C26 C27 C28 no distance stored
extrude "Extrude187" cut sketch "Sketch38" profile of C13 C16 C17 C18 C23 C24 C25 C26 C27 C28 C29 C30 C31 C32 C33 no distance stored from offset 6
chamfer "Chamfer44" distance 2
chamfer "Chamfer45" distance 0.5
extrude "Extrude188" cut sketch "Sketch38" profile of C13 C16 C17 C18 C23 C24 C25 C26 C27 C28 no distance stored from offset -11 (= "-6 mm - 5 mm")
extrude "Extrude189" cut sketch "Sketch38" profile of C13 C16 C17 C18 C23 C29 C30 C31 C32 C33 no distance stored from offset -16 (= "-6 mm - 10 mm")
chamfer "Chamfer46" distance 1
chamfer "Chamfer47" distance 1
chamfer "Chamfer48" distance 0.5
component_insert "Component Insert"
sketch "Motor Plane" plane through (0, 0, -20) normal (0, 0, -1) x axis (1, 0, 0)
  line L1 (-24.8, 36.8) -> (-24.8, 15.8)
  line L2 (-40.5, 36.8) -> (-24.8, 36.8)
  line L3 (-40.5, -47.4) -> (-40.5, 36.8)
  line L4 (-17.6, -47.4) -> (-40.5, -47.4)
  line L5 (-17.6, -27.4) -> (-17.6, -47.4)
  line L6 (27.5, -27.4) -> (-17.6, -27.4)
  line L7 (27.5, 36.8) -> (27.5, -27.4)
  line L8 (-21.8, 36.8) -> (27.5, 36.8)
  line L9 (-21.8, 33.0249) -> (-21.8, 36.8)
  line L10 (-21.8, 14.8) -> (-21.8, 28.5751)
  line L11 (-34.13, 12.8) -> (-23.8, 12.8)
  line L12 (-35.13, -13.8) -> (-35.13, 11.8)
  line L13 (-37.13, 11.8) -> (-37.13, -13.8)
  line L14 (-25.8, 14.8) -> (-34.13, 14.8)
  line L15 (-17.6, -97.4) -> (-17.6, -47.4)
  line L16 (-32.3, -97.4) -> (-17.6, -97.4)
  line L17 (-32.3, -47.4) -> (-32.3, -97.4)
  line L18 (42.4, -87.4) -> (-17.6, -87.4)
  line L19 (42.4, -27.4) -> (42.4, -87.4)
  line L20 (27.5, -27.4) -> (42.4, -27.4)
  line L21 (42.4, 27.3) -> (27.5, 27.3)
  line L22 (42.4, -97.4) -> (42.4, 27.3)
  line L23 (-17.6, -97.4) -> (42.4, -97.4)
  line L24 (40.8319, -85.8319) -> (-15.5681, -85.8319)
  line L25 (87.5, 27.5) -> (-32.5, 27.5)
  line L26 (40.8319, -29.4319) -> (40.8319, -85.8319)
  line L27 (-15.5681, -85.8319) -> (-15.5681, -29.4319)
  line L28 (-15.5681, -29.4319) -> (40.8319, -29.4319)
  line L29 (36.6558, -14.6378) -> (18.5441, -59.9928)
  line L30 (-27.1727, -28.6279) -> (8.2492, -62.2493)
  line L31 (-17.6, -62.6319) -> (-5.802, -62.6319)
  line L32 (-32.3, -83.6319) -> (-17.6, -83.6319)
  line L33 (6.2436, -39.6319) -> (-17.6, -39.6319)
  line L34 (-16.6, -83.6319) -> (-17.6, -83.6319)
  line L35 (-16.6, -62.6319) -> (-16.6, -83.6319)
  line L36 (-16.6, -47.4) -> (-16.6, -39.6319)
  line L37 (-17.6, -47.4) -> (-16.6, -47.4)
  line L38 (-16.6, -37.3) -> (-16.6, -39.6319)
  line L39 (-17.6, -37.3) -> (-16.6, -37.3)
  circle C1 centre (22.5, 22.5) radius 4.25
  circle C2 centre (-12.5, -22.5) radius 4.25
  circle C3 centre (-32.8, -22.8) radius 3
  circle C4 centre (-32.8, 22.8) radius 3
  arc A1 centre (-25.8, 15.8) radius 1 clockwise from (-24.8, 15.8) to (-25.8, 14.8)
  arc A2 centre (-21.5, 33.0249) radius 0.3 clockwise from (-21.3179, 32.7865) to (-21.8, 33.0249)
  arc A3 centre (-19.8, 30.8) radius 2.5 clockwise from (-21.3179, 32.7865) to (-21.3179, 28.8135)
  arc A4 centre (-21.5, 28.5751) radius 0.3 clockwise from (-21.8, 28.5751) to (-21.3179, 28.8135)
  arc A5 centre (-23.8, 14.8) radius 2 clockwise from (-21.8, 14.8) to (-23.8, 12.8)
  arc A6 centre (-34.13, 11.8) radius 1 clockwise from (-35.13, 11.8) to (-34.13, 12.8)
  arc A7 centre (-36.13, -13.8) radius 1 clockwise from (-35.13, -13.8) to (-37.13, -13.8)
  arc A8 centre (-34.13, 11.8) radius 3 clockwise from (-37.13, 11.8) to (-34.13, 14.8)
  circle C5 centre (0, 0) radius 21
  circle C6 centre (-27.5, -42.4) radius 4.25
  circle C7 centre (-12.5, 22.5) radius 4.25
  circle C8 centre (22.5, -22.5) radius 4.25
  circle C9 centre (36.2019, -81.2019) radius 3.95
  circle C10 centre (36.2019, -34.0619) radius 3.95
  circle C11 centre (-10.9381, -81.2019) radius 3.95
  circle C12 centre (-10.9381, -34.0619) radius 3.95
  circle C13 centre (12.6319, -57.6319) radius 19.1
  circle C14 centre (-27.5, -92.4) radius 2.7
  circle C15 centre (37.5, -92.4) radius 2.7
  circle C16 centre (37.5, 22.5) radius 2.7
  circle C17 centre (37.5, -92.4) radius 3.7
  circle C18 centre (-27.5, -92.4) radius 3.7
  circle C19 centre (37.5, 22.5) radius 3.7
  circle C20 centre (37.5, -22.5) radius 2.7
  circle C21 centre (37.5, -22.5) radius 3.7
  circle C22 centre (-26.8681, -75.6319) radius 2.7
  circle C23 centre (-26.8681, -50.6319) radius 2.7
  point P12 (-17.6, -47.4)
  point P39 (-17.6, -47.4)
  point P42 (-32.3, -47.4)
  point P44 (-17.6, -87.4)
  point P14 (27.5, -27.4)
  point P47 (27.5, -27.4)
  point P52 (12.6319, -57.6319)
  point P53 (12.6319, -57.6319)
  point P48 (36.2019, -81.2019)
  point P54 (36.2019, -81.2019)
  point P49 (36.2019, -34.0619)
  point P55 (36.2019, -34.0619)
  point P51 (-10.9381, -34.0619)
  point P56 (-10.9381, -34.0619)
  point P50 (-10.9381, -81.2019)
  point P57 (-10.9381, -81.2019)
  point P58 (27.5, 27.3)
  point P40 (-17.6, -97.4)
  point P61 (-17.6, -97.4)
  point P67 (37.5, 22.5)
  point P69 (22.5, 22.5)
  point P64 (-27.5, -92.4)
  point P66 (37.5, -92.4)
  point P76 (37.5, -22.5)
  point P77 (22.5, -22.5)
  point P72 (37.5, -92.4)
  point P88 (-5.802, -62.6319)
  point P89 (-17.6, -62.6319)
  point P90 (-17.6, -83.6319)
  point P91 (-32.3, -83.6319)
  point P92 (-17.6, -39.6319)
  point P93 (6.2436, -39.6319)
  point P95 (-16.6, -62.6319)
  point P96 (-16.6, -39.6319)
  point P98 (-17.6, -47.4)
  point P100 (-17.6, -37.3)
  point P101 (-17.6, -37.3)
  point P102 (-26.8681, -75.6319)
  point P103 (-26.8681, -50.6319)
  point P46 (42.4, -27.4)
  point P43 (-32.5, -52.5)
  point P65 (-27.5, -42.4)
  point P68 (22.5, 22.5)
  point P45 (42.4, -87.4)
  point P74 (37.5, 22.5)
  coincident P12 P39
  perpendicular L4 L15
  perpendicular L5 L16
  perpendicular L16 L17
  coincident L4 P42
  coincident L15 P44
  perpendicular L15 L18
  perpendicular L18 L19
  perpendicular L15 L20
  coincident P14 P47
  coincident P52 P53
  coincident P48 P54
  coincident P49 P55
  coincident P51 P56
  coincident P50 P57
  equal C9 C11
  equal C9 C12
  equal C9 C10
  coincident L7 P58
  perpendicular L7 L21
  perpendicular L21 L22
  perpendicular L22 L23
  coincident P40 P61
  equal C14 C15
  horizontal P67 P69
  equal C14 C16
  horizontal P64 P66
  concentric C15 C17
  concentric C14 C18
  concentric C16 C19
  equal C17 C19
  equal C17 C18
  concentric C20 C21
  vertical P67 P76
  horizontal P76 P77
  equal C16 C20
  equal C19 C21
  vertical P67 P72
  coincident C13 P88
  coincident L15 P89
  perpendicular L15 L31
  coincident L15 P90
  coincident L17 P91
  perpendicular L17 L32
  coincident L5 P92
  perpendicular L5 L33
  coincident C13 P93
  perpendicular L15 L34
  coincident L31 P95
  perpendicular L31 L35
  coincident L33 P96
  perpendicular L33 L36
  perpendicular L5 L37
  coincident P39 P98
  coincident P95 L36
  perpendicular L33 L38
  coincident L5 P100
  perpendicular L5 L39
  coincident P100 P101
  vertical P102 P103
  equal C22 C23
  coincident P46 L22
  dimension "d1739" distance L17 P43 = 0.2
  dimension "d1740" diameter C9 = 7.9
  dimension "d1741" diameter C13 = 38.2
  dimension "d1744" distance P43 P64 = 5
  dimension "d1745" distance P64 P65 = 50
  dimension "d1746" distance L16 P64 = 5
  dimension "d1748" distance P67 P68 = 15
  dimension "d1749" distance L21 L25 = 0.2
  dimension "d1751" diameter C14 = 5.4 (= "hw_m3insert_d")
  dimension "d1752" distance C14 C18 = 1
  dimension "d1769" distance P44 P45 = 60
  dimension "d1770" distance P45 P46 = 60
  dimension "d1771" distance L15 P65 = 9.9
  dimension "d1792" distance P52 L31 = 5
  dimension "d1793" distance L31 L32 = 21
  dimension "d1794" distance P52 L33 = 18
  dimension "d1800" distance P90 L35 = 1
  dimension "d1807" distance P102 P103 = 25
  dimension "d1808" diameter C22 = 5.4 (= "hw_m3insert_d")
  dimension "d1809" distance P53 P103 = 39.5 (= "midler_x")
  dimension "d1811" distance P53 P102 = 18 (= "midler_y")
  dimension "d1853" distance L22 P74 = 4.9
extrude "Extrude191" add sketch "Motor Plane" profile of L4 L5 L6 L7 L15 L16 L17 L18 L19 L20 C9 C10 C11 C12 C13 L21 L22 L23 C14 C15 C16 C17 C18 C19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 against normal blind 7.5
extrude "Extrude192" add sketch "Motor Plane" profile of L4 L7 L15 L16 L17 L18 L20 L21 L22 L23 C14 C15 C16 C17 C18 C19 C20 C21 L32 C22 C23 to an object
extrude "Extrude193" cut sketch "Motor Plane" profile of C14 C15 C16 C20 no distance stored
extrude "Extrude194" cut sketch "Motor Plane" profile of C14 C15 C16 C17 C18 C19 C20 C21 against normal blind 5
extrude "Extrude198" cut sketch "Motor Plane" profile of L4 L5 L15 L17 C13 L27 L30 L31 L32 L33 L34 L35 L36 L37 L38 L39 to an object
extrude "Extrude199" sketch "Sketch38" profile of L10 L52 C23 L65 L66 L67 L68 C24 C29 to an object
extrude "Extrude200" sketch "Sketch38" profile of C23 C24 blind 5
chamfer "Chamfer54" distance 1
chamfer "Chamfer55" distance 0.5
fillet "Fillet132" radius 2
extrude "Extrude201" sketch "Motor Plane" profile of C22 C23 to an object
chamfer "Chamfer56" distance 0.5
joint "Assemble1" OffsetX 0 OffsetY 0 OffsetZ 0 AngleZ 0 alignAngle 180 alignOffsetX 0 alignOffsetY 0 alignOffsetZ 0
chamfer "Chamfer50" distance 1
chamfer "Chamfer51" distance 0.5
chamfer "Chamfer52" distance 0.5
chamfer "Chamfer53" distance 0.7
fillet "Fillet117" radius 1
extrude "Extrude195" sketch "Motor Plane" profile of C9 C10 C11 C12 C13 L24 L26 L27 L28 blind -76 from offset 0.1 bodies "Motor Dummy"
fillet "Fillet118" radius 1
extrude "Extrude196" add of existing geometry to an object
fillet "Fillet119" radius 2
fillet "Fillet120" radius 1
fillet "Fillet121" radius 1
fillet "Fillet122" radius 2
fillet "Fillet123" radius 1
fillet "Fillet124" radius 1
fillet "Fillet125" radius 1
fillet "Fillet126" radius 1
fillet "Fillet127" radius 2
fillet "Fillet128" radius 1
fillet "Fillet129" radius 2
extrude "Extrude197" add of existing geometry to an object
fillet "Fillet130" radius 2
fillet "Fillet131" radius 2
chamfer "Chamfer57" distance 1.5
fillet "Fillet133" radius 2
fillet "Fillet135" radius 2
sketch "Sketch48" plane through (0, -36.8, 0) normal (0, -1, 0) x axis (1, 0, 0)
  line L1 (26.5, -10) -> (26.5, -20)
  line L2 (-21.8, -10) -> (26.5, -10)
  line L3 (-21.8, -20) -> (-21.8, -10)
  line L4 (26.5, -20) -> (-21.8, -20)
  line L5 (-11.8, -10) -> (-11.8, -20)
  line L6 (-16.8, -15) -> (-11.8, -15)
  line L7 (-16.8, -20) -> (-16.8, -15)
  line L8 (-21.8, -15) -> (-16.8, -15)
  circle C1 centre (-16.8, -15) radius 3
  circle C2 centre (-16.8, -15) radius 4
  circle C3 centre (-16.8, -15) radius 7.5
  point P6 (-11.8, -20)
  point P7 (-11.8, -10)
  point P8 (-11.8, -15)
  point P10 (-16.8, -20)
  point P11 (-21.8, -15)
  point P9 (-16.8, -15)
  point P12 (-16.8, -15)
  point P4 (-21.8, -10)
  coincident L4 P6
  coincident L2 P7
  perpendicular L2 L5
  midpoint L5 P8
  perpendicular L5 L6
  perpendicular L6 L7
  coincident L4 P10
  perpendicular L7 L8
  coincident L3 P11
  equal L6 L8
  coincident P9 P12
  concentric C1 C2
  concentric C2 C3
  dimension "d1857" distance P4 L5 = 10
  dimension "d1858" diameter C1 = 6 (= "hw_m4insert_d")
  dimension "d1859" distance C1 C2 = 1
  dimension "d1871" diameter C3 = 15
extrude "Extrude206" add sketch "Sketch48" profile of L2 L3 L4 L5 C1 C2 along normal blind 15.7
extrude "Extrude207" sketch "Sketch48" profile of C1 blind -8
extrude "Extrude208" sketch "Sketch48" profile of C1 C2 blind 0.5
chamfer "Chamfer60" distance 0.5
chamfer "Chamfer61" distance 0.5
fillet "Fillet136" radius 2
extrude "Extrude209" sketch "Sketch48" profile of L2 L3 L4 L5 C1 C2 C3 blind 15
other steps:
joint_origin "JointOrigin1" OffsetX 0 OffsetY 0 OffsetZ 0 AngleZ 0
named bodies: "Rear Set", "Front Set", "Drive Reduce", "Drive Pinion", "Drive Cap", "Motor Dummy"

design "rct-dex-toes"
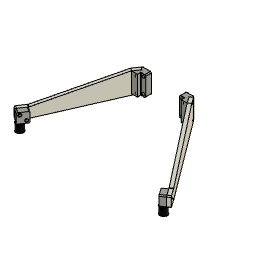
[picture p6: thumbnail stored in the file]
parameter "t_sheet_MAIN" = 6.7 comment "thickness of *most* of the gantry material"
parameter "t_sheet_SECOND" = 6.35 (= "1 / 4 * 1") comment "thickness of the webs"
parameter "od_bearings" = 16
parameter "id_bearings" = 5
parameter "t_bearings" = 5
parameter "p_belt" = 2
parameter "w_belt" = 10
parameter "t_belt" = 1.4
parameter "l_top_belt_to_rail" = 3
parameter "r_cutoutTool" = 2.05 (= "4.1 mm / 2")
parameter "hw_m3_thru" = 3.5
parameter "hw_m3_head" = 5.5
parameter "hw_m3_washer" = 7
parameter "hw_m3_thread" = 2.5
parameter "tab_breather" = 0.2 comment "tab clearance"
parameter "hw_m5_thread" = 4.2
parameter "hw_m5_head" = 8.5
parameter "hw_m5_washer" = 10
parameter "hw_m5_thru" = 5.25
parameter "hw_m6_thru" = 6.5
parameter "hw_m6_head" = 10
parameter "hw_m6_washer" = 12
parameter "l_beltblock" = 15
parameter "hw_plstf6_thread" = 2.94
parameter "hw_plstf6_thru" = 4
parameter "hw_plstf6_head" = 6.86
parameter "hw_plstf6_washer" = 7.92
parameter "hw_m3_flathead" = 6
parameter "hw_m4insert_d" = 6
parameter "hw_m4insert_l" = 4.8
parameter "hw_m4_tappedwj" = 3.3
parameter "hw_m4_thru" = 4.25
parameter "hw_m4_head" = 7
parameter "hw_m4_headheight" = 4
parameter "preload_bearings" = 0.55
parameter "hw_m3insert_d" = 5.4
parameter "hw_m3insert_l" = 3.8
parameter "dist_clearance" = 0.5
parameter "hw_shoulder_headDiameter" = 9
parameter "hw_shoulder_headHeight" = 4
parameter "l_travel" = 405 comment "will be rounded to 10s"
parameter "User Parameter" = 0 (= "min 10")
parameter "nh_rail_width" = "nh_gantry_width - 3"
parameter "l_shoulder_thread" = 10
parameter "hw_n6_thru" = 4.064
parameter "hw_n6_thread" = 3.1
parameter "hw_n6_flathead" = 6.6548
parameter "hw_n6_head" = 6.858
parameter "carriage_offsets" = 0.25
parameter "hw_momentPin_reald" = 3.683
parameter "pinch_by" = 0.2
parameter "d285" = 2
parameter "d344" = 3.5
parameter "d482" = 3.35 (= "t_sheet_MAIN / 2")
parameter "d578" = 0.5
parameter "d683" = 3.683 (= "hw_momentPin_reald")
parameter "d689" = 0.5
parameter "d698" = 5
parameter "d705" = 3.5415 (= "d683 / 2 + 1.7 mm")
parameter "d837" = 0.25
parameter "d1475" = 0.1
parameter "d1562" = 5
